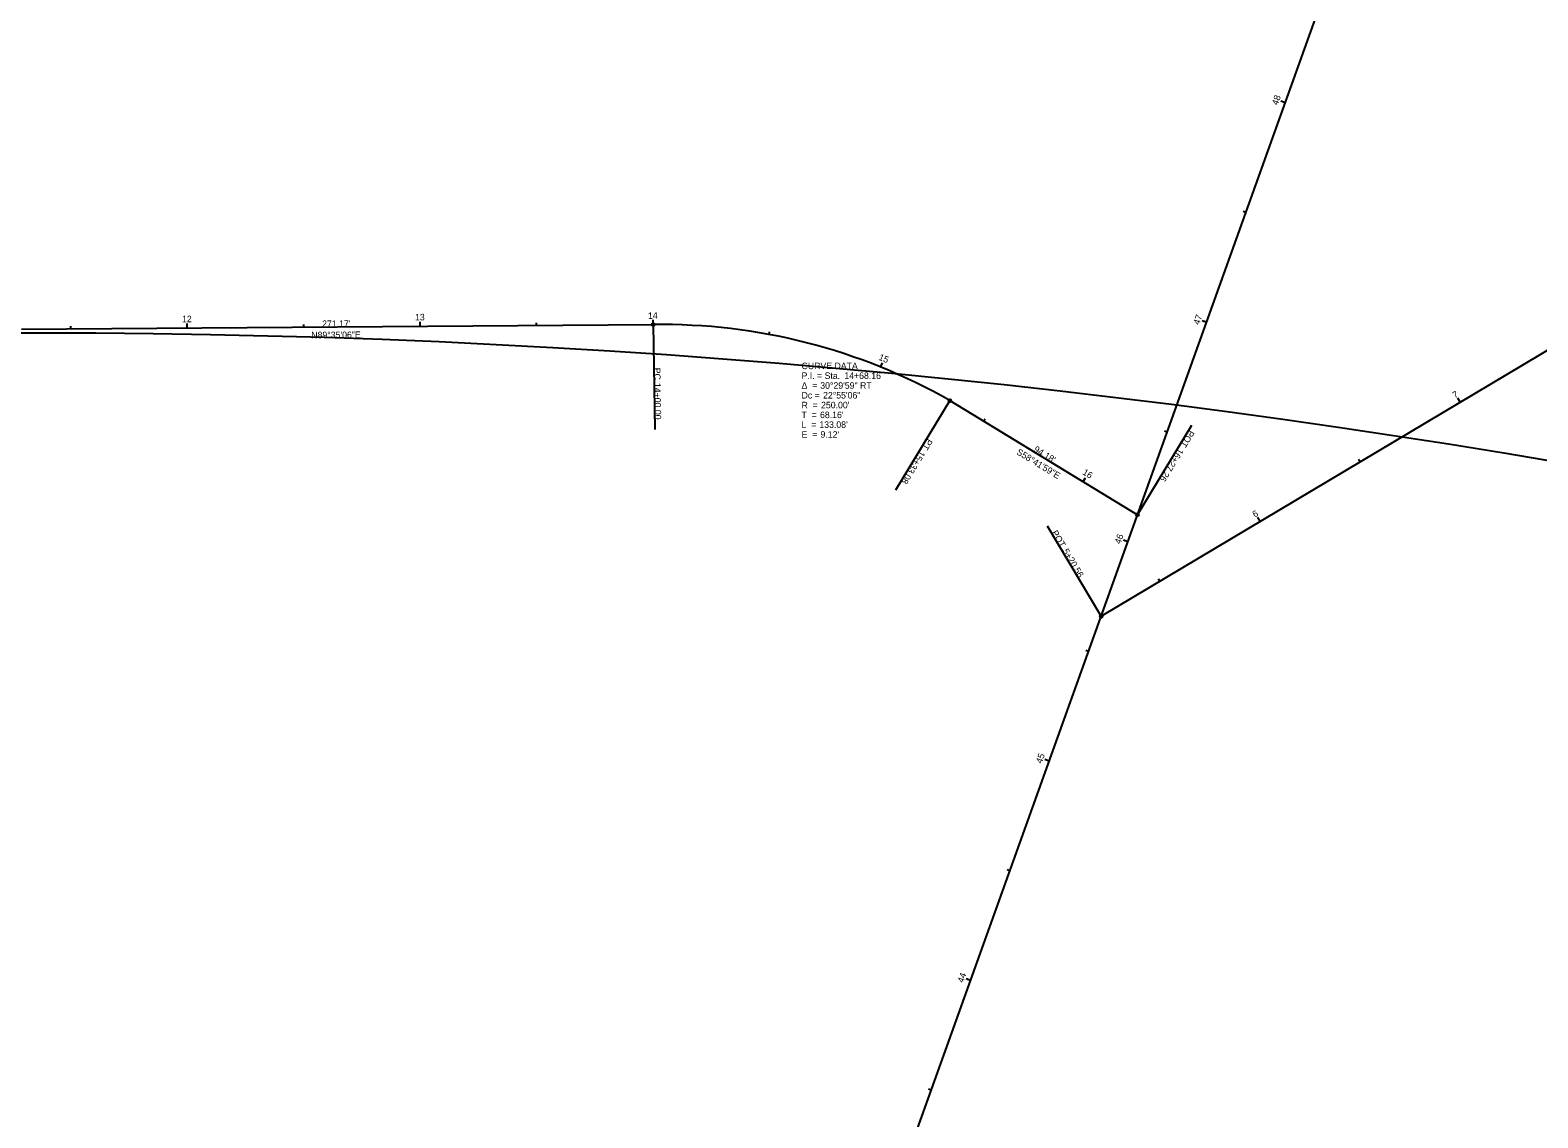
# Model space of a CAD drawing. Extents: x 2255781 to 2266449, y 734189 to 743342.
# Drawn here: x 2262626 to 2263273, y 741492 to 741958 of the extents above; entities that cross this region are included whole.
import ezdxf

# ---------------------------------------------------------------- set-up
doc = ezdxf.new("R2010")
doc.units = 0
for name, color, linetype in [('GE_X_Alignment', 7, 'Continuous'), ('GE_X_Alignment_1000_Bearings', 7, 'Continuous'), ('GE_X_Alignment_1000_Cardinal_Points', 7, 'Continuous'), ('GE_X_Alignment_1000_Distances', 7, 'Continuous'), ('GE_X_Alignment_1000_Stations', 7, 'Continuous'), ('GE_X_Alignment_100_Bearings', 7, 'Continuous'), ('GE_X_Alignment_100_Cardinal_Points', 7, 'Continuous'), ('GE_X_Alignment_100_Curve_Data', 7, 'Continuous'), ('GE_X_Alignment_100_Distances', 7, 'Continuous'), ('GE_X_Alignment_100_Stations', 7, 'Continuous'), ('GE_X_Alignment_500_Bearings', 7, 'Continuous'), ('GE_X_Alignment_500_Cardinal_Points', 7, 'Continuous'), ('GE_X_Alignment_500_Curve_Data', 7, 'Continuous'), ('GE_X_Alignment_500_Distances', 7, 'Continuous'), ('GE_X_Alignment_500_Stations', 7, 'Continuous'), ('RW_X_CL_500_Bearings', 7, 'Continuous')]:
    doc.layers.add(name, color=color, linetype=linetype)

msp = doc.modelspace()

# ---------------------------------------------------------------- linework, layer by layer
at = {"layer": 'GE_X_Alignment'}
for p, q in [((2262767.69, 740821.08), (2263234.07, 742121.49)), ((2263085.36, 741706.84), (2263491.92, 741949.06)), ((2262621.95, 741830), (2262893.11, 741831.97)), ((2263020.52, 741799.37), (2263100.99, 741750.44))]:
    msp.add_line(p, q, dxfattribs=at)
msp.add_arc((2262897.03, 741582), 250, 60.39853, 90.89822, dxfattribs=at)
at = {"layer": 'GE_X_Alignment_1000_Cardinal_Points'}
for p, q in [((2262893.11, 741831.97), (2262893.82, 741786.97)), ((2263020.52, 741799.37), (2262997.14, 741760.92)), ((2263100.99, 741750.44), (2263124.37, 741788.89)), ((2263085.36, 741706.84), (2263062.32, 741745.5))]:
    msp.add_line(p, q, dxfattribs=at)
for centre in [(2262893.11, 741831.97), (2263020.52, 741799.37), (2263100.99, 741750.44), (2263085.36, 741706.84)]:
    msp.add_circle(centre, 0.6, dxfattribs=at)
at = {"layer": 'GE_X_Alignment_1000_Stations'}
for p, q in [((2262990.76, 741813.76), (2262991.21, 741814.87)), ((2263063.08, 741644.71), (2263061.95, 741645.12))]:
    msp.add_line(p, q, dxfattribs=at)
at = {"layer": 'GE_X_Alignment_100_Cardinal_Points'}
for p, q in [((2262893.11, 741831.97), (2262893.82, 741786.97)), ((2263020.52, 741799.37), (2262997.14, 741760.92)), ((2263100.99, 741750.44), (2263124.37, 741788.89)), ((2263085.36, 741706.84), (2263062.32, 741745.5))]:
    msp.add_line(p, q, dxfattribs=at)
for centre in [(2262893.11, 741831.97), (2263020.52, 741799.37), (2263100.99, 741750.44), (2263085.36, 741706.84)]:
    msp.add_circle(centre, 0.6, dxfattribs=at)
at = {"layer": 'GE_X_Alignment_100_Stations'}
for p, q in [((2263164.35, 741927.1), (2263162.47, 741927.78)), ((2263147.47, 741880.04), (2263146.34, 741880.44)), ((2262693.12, 741830.52), (2262693.1, 741832.52)), ((2262743.11, 741830.88), (2262743.11, 741832.08)), ((2262793.11, 741831.24), (2262793.1, 741833.24)), ((2262843.11, 741831.61), (2262843.1, 741832.81)), ((2262893.11, 741831.97), (2262893.08, 741833.97)), ((2263130.59, 741832.97), (2263128.71, 741833.65)), ((2262643.12, 741830.16), (2262643.11, 741831.36)), ((2262942.85, 741827.76), (2262943.07, 741828.94)), ((2262990.76, 741813.76), (2262991.51, 741815.62)), ((2263239.51, 741798.68), (2263238.49, 741800.4)), ((2263034.98, 741790.58), (2263035.6, 741791.6)), ((2263113.71, 741785.91), (2263112.58, 741786.31)), ((2263196.56, 741773.09), (2263195.94, 741774.12)), ((2263077.7, 741764.6), (2263078.74, 741766.31)), ((2263153.6, 741747.5), (2263152.58, 741749.22)), ((2263096.83, 741738.84), (2263094.95, 741739.52)), ((2263110.65, 741721.91), (2263110.03, 741722.94)), ((2263079.95, 741691.78), (2263078.83, 741692.18)), ((2263063.08, 741644.71), (2263061.19, 741645.39)), ((2263046.2, 741597.65), (2263045.07, 741598.05)), ((2263029.32, 741550.58), (2263027.43, 741551.26)), ((2263012.44, 741503.52), (2263011.31, 741503.92))]:
    msp.add_line(p, q, dxfattribs=at)
at = {"layer": 'GE_X_Alignment_500_Cardinal_Points'}
for p, q in [((2262893.11, 741831.97), (2262893.82, 741786.97)), ((2263020.52, 741799.37), (2262997.14, 741760.92)), ((2263100.99, 741750.44), (2263124.37, 741788.89)), ((2263085.36, 741706.84), (2263062.32, 741745.5))]:
    msp.add_line(p, q, dxfattribs=at)
for centre in [(2262893.11, 741831.97), (2263020.52, 741799.37), (2263100.99, 741750.44), (2263085.36, 741706.84)]:
    msp.add_circle(centre, 0.6, dxfattribs=at)
at = {"layer": 'GE_X_Alignment_500_Stations'}
for p, q in [((2263164.35, 741927.1), (2263163.22, 741927.51)), ((2262693.12, 741830.52), (2262693.11, 741831.72)), ((2262793.11, 741831.24), (2262793.1, 741832.44)), ((2262893.11, 741831.97), (2262893.09, 741833.17)), ((2263130.59, 741832.97), (2263129.46, 741833.38)), ((2262990.76, 741813.76), (2262991.51, 741815.62)), ((2263239.51, 741798.68), (2263238.9, 741799.71)), ((2263077.7, 741764.6), (2263078.32, 741765.63)), ((2263153.6, 741747.5), (2263152.99, 741748.53)), ((2263096.83, 741738.84), (2263095.7, 741739.25)), ((2263063.08, 741644.71), (2263061.19, 741645.39)), ((2263029.32, 741550.58), (2263028.19, 741550.99))]:
    msp.add_line(p, q, dxfattribs=at)
at = {"layer": 'RW_X_CL_500_Bearings'}
msp.add_circle((2262629.16, 738008.76), 3819.72, dxfattribs=at)

# ---------------------------------------------------------------- texts
at = {"layer": 'GE_X_Alignment_1000_Bearings'}
for s, rotation, p in [('N89°35\'06"E', 0.41504, (2262746.38, 741826.1)), ('S58°41\'59"E', 328.69985, (2263048.8, 741776.56))]:
    msp.add_text(s, height=2.8, rotation=rotation, dxfattribs=at).set_placement(p)
at = {"layer": 'GE_X_Alignment_1000_Cardinal_Points'}
for s, rotation, p in [('PC', 270.89822, (2262893.45, 741813.46)), ('14+00.00', 270.89822, (2262893.55, 741806.94)), ('POT', 238.69985, (2263123.27, 741786.98)), ('PT', 238.69985, (2263010.83, 741783.34)), ('15+33.08', 238.69985, (2263007.67, 741778.14)), ('16+27.26', 238.69985, (2263118.52, 741779.18)), ('POT', 300.7854, (2263064.05, 741742.7)), ('5+20.56', 300.7854, (2263068.72, 741734.85))]:
    msp.add_text(s, height=2.8, rotation=rotation, dxfattribs=at).set_placement(p)
at = {"layer": 'GE_X_Alignment_1000_Distances'}
for s, rotation, p in [("271.17'", 0.41504, (2262751.04, 741830.94)), ("94.18'", 328.69985, (2263056.17, 741777.75))]:
    msp.add_text(s, height=2.8, rotation=rotation, dxfattribs=at).set_placement(p)
at = {"layer": 'GE_X_Alignment_100_Bearings'}
for s, rotation, p in [('N89°35\'06"E', 0.41504, (2262746.38, 741826.1)), ('S58°41\'59"E', 328.69985, (2263048.8, 741776.56))]:
    msp.add_text(s, height=2.8, rotation=rotation, dxfattribs=at).set_placement(p)
at = {"layer": 'GE_X_Alignment_100_Cardinal_Points'}
for s, rotation, p in [('PC', 270.89822, (2262893.45, 741813.46)), ('14+00.00', 270.89822, (2262893.55, 741806.94)), ('POT', 238.69985, (2263123.27, 741786.98)), ('PT', 238.69985, (2263010.83, 741783.34)), ('15+33.08', 238.69985, (2263007.67, 741778.14)), ('16+27.26', 238.69985, (2263118.52, 741779.18)), ('POT', 300.7854, (2263064.05, 741742.7)), ('5+20.56', 300.7854, (2263068.72, 741734.85))]:
    msp.add_text(s, height=2.8, rotation=rotation, dxfattribs=at).set_placement(p)
at = {"layer": 'GE_X_Alignment_100_Curve_Data'}
for s, p in [('CURVE DATA', (2262956.82, 741812.87)), ('CURVE DATA', (2262956.82, 741812.87)), ('Δ  = ', (2262956.82, 741804.47)), ('Δ  = ', (2262956.82, 741804.47)), ('P.I. = Sta. ', (2262956.82, 741808.67)), ('P.I. = Sta. ', (2262956.82, 741808.67)), ('30°29\'59" RT', (2262964.84, 741804.47)), ('30°29\'59" RT', (2262964.84, 741804.47)), ('14+68.16', (2262975.18, 741808.67)), ('14+68.16', (2262975.18, 741808.67)), ('Dc = ', (2262956.82, 741800.27)), ('Dc = ', (2262956.82, 741800.27)), ('22°55\'06"', (2262966.05, 741800.27)), ('22°55\'06"', (2262966.05, 741800.27)), ('T  = ', (2262956.82, 741791.87)), ('T  = ', (2262956.82, 741791.87)), ('R  = ', (2262956.82, 741796.07)), ('R  = ', (2262956.82, 741796.07)), ("68.16'", (2262964.75, 741791.87)), ("68.16'", (2262964.75, 741791.87)), ("250.00'", (2262965.18, 741796.07)), ("250.00'", (2262965.18, 741796.07)), ('L  = ', (2262956.82, 741787.67)), ('L  = ', (2262956.82, 741787.67)), ('E  = ', (2262956.82, 741783.47)), ('E  = ', (2262956.82, 741783.47)), ("133.08'", (2262964.46, 741787.67)), ("133.08'", (2262964.46, 741787.67)), ("9.12'", (2262964.97, 741783.47)), ("9.12'", (2262964.97, 741783.47))]:
    msp.add_text(s, height=2.8, dxfattribs=at).set_placement(p)
at = {"layer": 'GE_X_Alignment_100_Distances'}
for s, rotation, p in [("271.17'", 0.41504, (2262751.04, 741830.94)), ("94.18'", 328.69985, (2263056.17, 741777.75))]:
    msp.add_text(s, height=2.8, rotation=rotation, dxfattribs=at).set_placement(p)
at = {"layer": 'GE_X_Alignment_100_Stations'}
for s, rotation, p in [('48', 70.27027, (2263161.21, 741925.9)), ('12', 0.41504, (2262690.91, 741833)), ('13', 0.41504, (2262790.92, 741833.77)), ('14', 0.89822, (2262890.92, 741834.43)), ('47', 70.27027, (2263127.48, 741831.7)), ('15', 337.97991, (2262989.67, 741816.95)), ('7', 30.7854, (2263237.23, 741800.23)), ('16', 328.69985, (2263077.15, 741767.92)), ('6', 30.7854, (2263151.35, 741749.12)), ('46', 70.27027, (2263093.69, 741737.64)), ('45', 70.27027, (2263059.93, 741643.5)), ('44', 70.27027, (2263026.24, 741549.4))]:
    msp.add_text(s, height=2.8, rotation=rotation, dxfattribs=at).set_placement(p)
at = {"layer": 'GE_X_Alignment_500_Bearings'}
for s, rotation, p in [('N89°35\'06"E', 0.41504, (2262746.38, 741826.1)), ('S58°41\'59"E', 328.69985, (2263048.8, 741776.56))]:
    msp.add_text(s, height=2.8, rotation=rotation, dxfattribs=at).set_placement(p)
at = {"layer": 'GE_X_Alignment_500_Cardinal_Points'}
for s, rotation, p in [('PC', 270.89822, (2262893.45, 741813.46)), ('14+00.00', 270.89822, (2262893.55, 741806.94)), ('POT', 238.69985, (2263123.27, 741786.98)), ('PT', 238.69985, (2263010.83, 741783.34)), ('15+33.08', 238.69985, (2263007.67, 741778.14)), ('16+27.26', 238.69985, (2263118.52, 741779.18)), ('POT', 300.7854, (2263064.05, 741742.7)), ('5+20.56', 300.7854, (2263068.72, 741734.85))]:
    msp.add_text(s, height=2.8, rotation=rotation, dxfattribs=at).set_placement(p)
at = {"layer": 'GE_X_Alignment_500_Curve_Data'}
for s, p in [('CURVE DATA', (2262956.82, 741812.87)), ('Δ  = ', (2262956.82, 741804.47)), ('P.I. = Sta. ', (2262956.82, 741808.67)), ('30°29\'59" RT', (2262964.84, 741804.47)), ('14+68.16', (2262975.18, 741808.67)), ('Dc = ', (2262956.82, 741800.27)), ('22°55\'06"', (2262966.05, 741800.27)), ('T  = ', (2262956.82, 741791.87)), ('R  = ', (2262956.82, 741796.07)), ("68.16'", (2262964.75, 741791.87)), ("250.00'", (2262965.18, 741796.07)), ('L  = ', (2262956.82, 741787.67)), ('E  = ', (2262956.82, 741783.47)), ("133.08'", (2262964.46, 741787.67)), ("9.12'", (2262964.97, 741783.47))]:
    msp.add_text(s, height=2.8, dxfattribs=at).set_placement(p)
at = {"layer": 'GE_X_Alignment_500_Distances'}
for s, rotation, p in [("271.17'", 0.41504, (2262751.04, 741830.94)), ("94.18'", 328.69985, (2263056.17, 741777.75))]:
    msp.add_text(s, height=2.8, rotation=rotation, dxfattribs=at).set_placement(p)
at = {"layer": 'GE_X_Alignment_500_Stations'}
for s, rotation, p in [('15', 337.97991, (2262989.67, 741816.95)), ('45', 70.27027, (2263059.93, 741643.5))]:
    msp.add_text(s, height=2.8, rotation=rotation, dxfattribs=at).set_placement(p)

doc.saveas('drawing.dxf')
